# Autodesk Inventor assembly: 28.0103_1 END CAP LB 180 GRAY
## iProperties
Created: 2007-06
Part Number: 28.0103_1 END CAP LB 180 GRAY
Document SubType Name: Assembly
Designer: Andy Moles
Author: Andy Moles
